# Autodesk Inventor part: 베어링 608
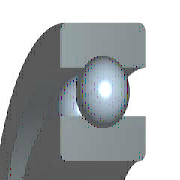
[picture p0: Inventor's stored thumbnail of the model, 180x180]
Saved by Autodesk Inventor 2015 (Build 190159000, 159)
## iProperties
IsCustomPart: 1
Created: 2012-02
Part Number: 베어링 608
Material: 강철, 연강
Description: 깊은 그루브 볼 베어링
Document SubType Name: Modeling
Standard: KS B 2023
Designer: mduedu
Standards Organization: KS
Language: ko-KR
Size Designation: 608 - 8 x 22 x 7
Categories: <MemberInstance><Categories><Category DisplayName="샤프트 부품" InternalName="7f7aeb1f-a693-4053-b835-cee3144e0d98" Mnemonic="SHFT"><Category DisplayName="베어링" Inter
Density: 1 g/cm^3
Appearance: 주황색
Author: mduedu
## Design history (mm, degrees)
sketch "스케치" dims "d0" = 3.64 (= -0.26 x WD + 0.26 x BD)
  geometry: L1 (1.68, 7.5)-(5.32, 7.5); L2 (3.5, 7.5)-(3.5, 5.68); L3 (3.5, 7.5)-(3.5, 9.32); L4 (2.148, 6.282)-(0, 6.282); L5 (0, 4)-(7, 4); L6 (2.148, 8.718)-(0, 8.718); L7 (0, 11)-(7, 11); L8 (7, 4)-(7, 6.282); L9 (4.852, 6.282)-(7, 6.282); L10 (4.852, 8.718)-(7, 8.718); L11 (7, 11)-(7, 8.718); L12 (-1.4, 0)-(8.4, 0) reference; L13 (0, -0.3)-(0, 5.3) reference
  constraints: 22 end point, 4 point on line, 2 collinear, 2 perpendicular, 2 symmetric about line, 1 midpoint, 1 parallel, 14 other
  dimensions: "d9" = 8 diameter of L5 L12 (= WD); "d11" = 22 diameter of L7 L12 (= BD); "d12" = 7 distance between parallel lines of L8 L13 (= KB); "d13" = 12.564 diameter of L9 L12 (= 0.326 x BD + 0.674 x WD)
revolve "본체" stored, may be unused: angle "d6" = 90 deg
revolve "볼" stored, may be unused: angle "d7" = 90 deg
pattern_circular "IDS_ARRAYBALL[SIMPL:T]" dims angle "d3" = 360 deg
body "Solid1"
fillet "모깎기1" dims "d1" = 0.3 (= KRS)
other parameters: "WD" = 8 [user parameter; used in 5 equation terms], "BD" = 22 [user parameter; used in 5 equation terms], "KB" = 7 [user parameter; used in 1 equation term], "KRS" = 0.3 [user parameter; used in 1 equation term], "d4" = 0, "d5" = 0, "d8" = 0, "d14" = 0, "d15" = 0, "BBA" = 0 [user parameter], "BC0" = 1370000 [user parameter], "BC" = 3250000 [user parameter], "BR" = 11 (= 0.5 x BD) [user parameter], "WR" = 4 (= 0.5 x WD) [user parameter]
